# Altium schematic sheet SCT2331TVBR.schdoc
size 127 x 101 mm
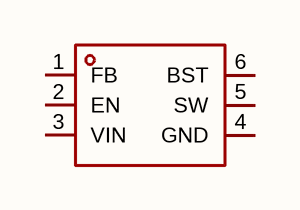
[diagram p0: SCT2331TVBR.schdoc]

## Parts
U?  sct2331tvbr  [SOT-23-6_L2.9-W1.6-P0.95-LS2.8-BR]  (value not drawn)

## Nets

Not connected (* = marked no-connect by the designer): U? 1(FB) 2(EN) 3(VIN) 4(GND) 5(SW) 6(BST)

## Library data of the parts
U? = sct2331tvbr: 功能类型:降压型;工作电压:3.8V~32V;输出电压:-;输出电流:3A;输出类型:可调;; Manufacturer: SCT(芯洲科技); AddInBom: yes; ModelId: 18da8f6c14a34920b3e136b5c401a119; ModelName: SOT-23-6_L2.9-W1.6-H1.5-LS2.8-P0.95; ModelTransform: 110.73671,114.173,0,180,0,0,0.001,-0.003,0; Function: 降压型; Output Current: 3A; Frequency - Switching: 400kHz; Synchronous Rectifier: 是; Number of Outputs: 1; Topology: 降压式; Quiescent Current: 250uA; Switch tube (built-in/external): 内置; Output Type: 可调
